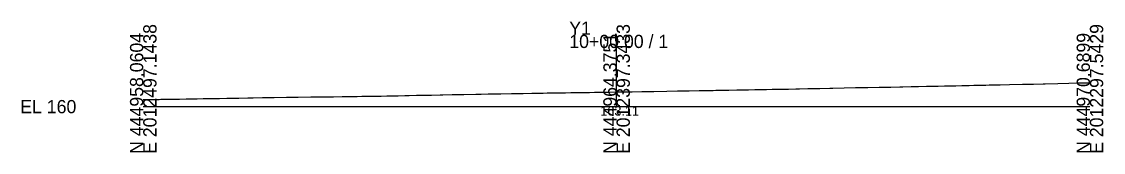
# Model space of a CAD drawing. Extents: x -26 to 3203, y -10 to 9517.
# Drawn here: x -25.7 to 202.8, y -9.7 to 18 of the extents above; entities that cross this region are included whole.
import ezdxf

# ---------------------------------------------------------------- set-up
doc = ezdxf.new("R2010")
doc.units = 0
for name, color, linetype in [('Default', 7, 'Continuous'), ('Exist Cross Section Cell', 7, 'Continuous'), ('Exist XS Center Line Elevation Label', 7, 'Continuous'), ('Exist XS Ground Line', 7, 'Continuous')]:
    doc.layers.add(name, color=color, linetype=linetype)

msp = doc.modelspace()

# ---------------------------------------------------------------- linework, layer by layer
at = {"layer": 'Exist Cross Section Cell'}
for p, q in [((100, 0), (100, 15.21)), ((0, 0), (100, 0)), ((100, 0), (200, 0))]:
    msp.add_line(p, q, dxfattribs=at)
at = {"layer": 'Exist XS Ground Line'}
msp.add_lwpolyline([(0, 1.48), (1.99, 1.52), (2.63, 1.53), (3.35, 1.54), (3.75, 1.55), (5.14, 1.57), (6.71, 1.59), (7.64, 1.61), (9.07, 1.63), (10.15, 1.65), (11.38, 1.67), (12.66, 1.69), (13.78, 1.71), (15.16, 1.74), (16.14, 1.75), (17.66, 1.77), (18.5, 1.79), (20.17, 1.82), (22.07, 1.86), (22.67, 1.87), (23.21, 1.88), (25.18, 1.9), (27.68, 1.93), (30.27, 1.97), (31.69, 1.99), (32.76, 2.01), (35.44, 2.04), (37.7, 2.07), (38.11, 2.07), (40.21, 2.1), (42.05, 2.13), (42.71, 2.14), (43.47, 2.15), (45.22, 2.17), (46.15, 2.19), (47.72, 2.21), (48.82, 2.23), (50.23, 2.24), (51.47, 2.27), (52.73, 2.29), (53.83, 2.31), (55.24, 2.34), (56.2, 2.37), (57.74, 2.4), (59.49, 2.44), (60.25, 2.45), (60.91, 2.46), (62.75, 2.5), (63.27, 2.51), (65.26, 2.55), (65.64, 2.55), (67.76, 2.59), (70.26, 2.63), (71.4, 2.66), (72.87, 2.68), (75.56, 2.73), (77.78, 2.76), (79.74, 2.79), (80.28, 2.8), (82.11, 2.84), (82.79, 2.85), (84.47, 2.87), (85.3, 2.89), (86.82, 2.91), (87.8, 2.93), (89.19, 2.95), (90.31, 2.96), (91.58, 2.98), (92.81, 3), (94.27, 3.02), (95.32, 3.04), (96.96, 3.06), (97.82, 3.07), (98.59, 3.08), (100, 3.11), (100.33, 3.11), (100.95, 3.12), (102.84, 3.14), (103.32, 3.15), (105.34, 3.18), (107.84, 3.23), (110.63, 3.28), (112.85, 3.32), (115.36, 3.36), (117.46, 3.39), (117.86, 3.4), (119.81, 3.44), (120.37, 3.45), (121, 3.46), (122.87, 3.49), (123.7, 3.5), (125.37, 3.53), (126.87, 3.56), (127.88, 3.58), (129.23, 3.6), (130.39, 3.62), (131.69, 3.65), (132.89, 3.67), (134.39, 3.7), (135.4, 3.71), (136.29, 3.73), (137.9, 3.77), (138.65, 3.78), (140.41, 3.81), (141.01, 3.82), (142.91, 3.87), (145.08, 3.91), (145.71, 3.92), (148.06, 3.97), (150.5, 4.02), (153.09, 4.06), (155.44, 4.1), (155.78, 4.11), (157.94, 4.15), (159.85, 4.19), (160.45, 4.2), (162.21, 4.24), (162.95, 4.25), (163.79, 4.27), (165.46, 4.31), (166.48, 4.33), (167.96, 4.36), (169.27, 4.38), (170.47, 4.41), (171.64, 4.43), (172.97, 4.46), (174.49, 4.49), (175.48, 4.51), (177.18, 4.55), (177.98, 4.56), (178.68, 4.58), (180.48, 4.62), (181.05, 4.63), (182.99, 4.67), (185.76, 4.74), (188.11, 4.79), (190.14, 4.84), (190.52, 4.85), (193.22, 4.91), (195.51, 4.96), (197.54, 5.01), (198.02, 5.02), (200, 5.07)], dxfattribs=at)

# ---------------------------------------------------------------- texts
at = {"layer": 'Default'}
msp.add_text('-', height=0.0001, dxfattribs=at).set_placement((0, 0))
at = {"layer": 'Exist Cross Section Cell'}
for s, p in [('E 2012497.1438', (2.8, -10)), ('E 2012397.3433', (102.8, -10)), ('E 2012297.5429', (202.8, -10)), ('N 444958.0604', (0, -10)), ('N 444964.3751', (100, -10)), ('N 444970.6899', (200, -10))]:
    msp.add_text(s, height=2.8, rotation=90, dxfattribs=at).set_placement(p)
for s, p in [('Y1', (90, 15.21)), ('10+00.00 / 1', (90, 12.41)), ('EL 160', (-26, -1.4))]:
    msp.add_text(s, height=2.8, dxfattribs=at).set_placement(p)
at = {"layer": 'Exist XS Center Line Elevation Label'}
msp.add_text('163.11', height=2, dxfattribs=at).set_placement((96.56, -1.89))

doc.saveas('drawing.dxf')
